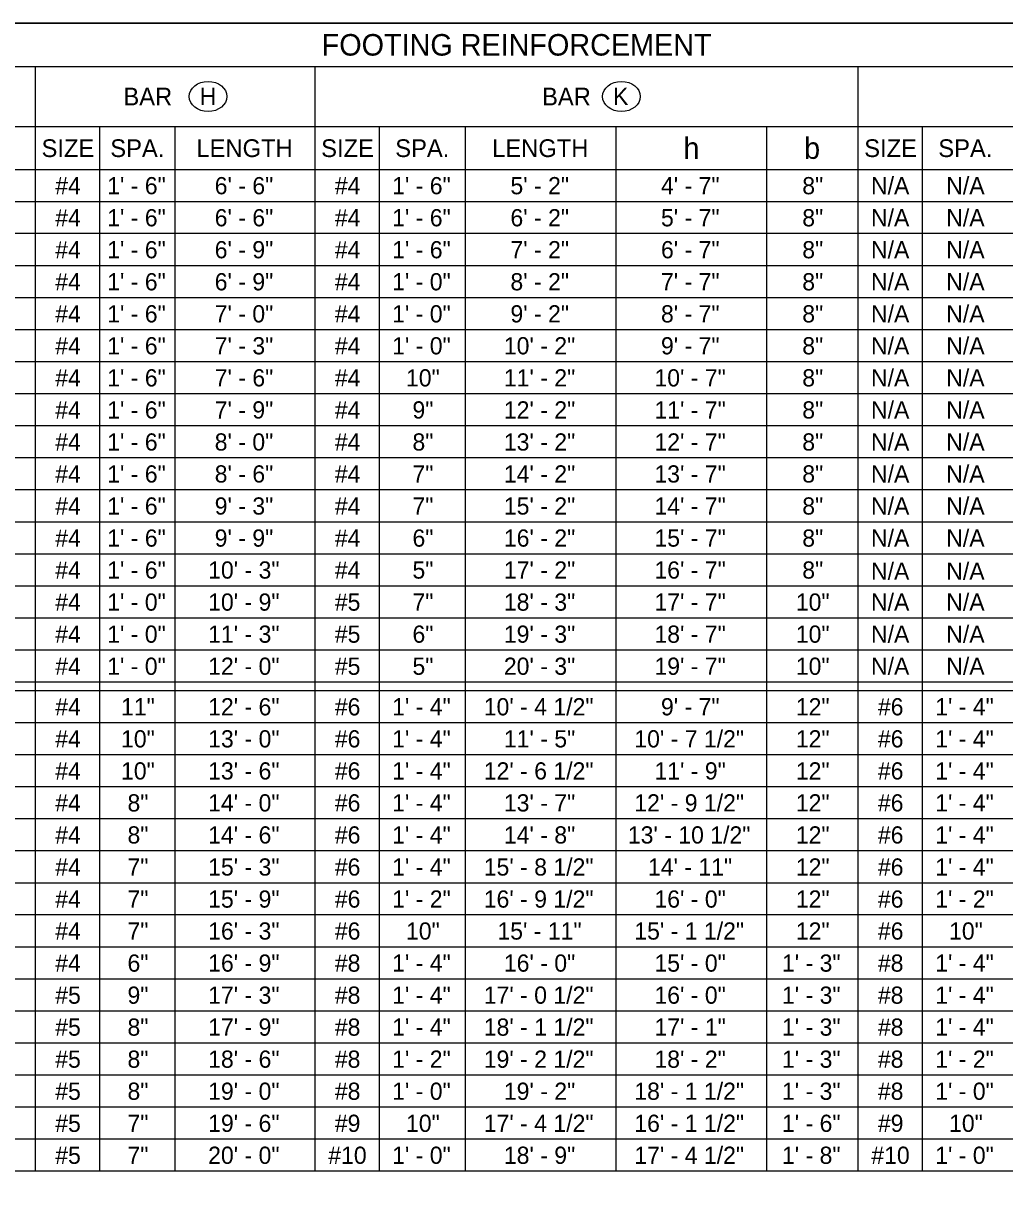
# Model space of a CAD drawing. Extents: x 99862 to 103151, y 100000 to 105076.
# Drawn here: x 100848 to 101760, y 103992 to 105076 of the extents above; entities that cross this region are included whole.
import ezdxf

# ---------------------------------------------------------------- set-up
doc = ezdxf.new("R2010")
doc.units = 0
for name, color, linetype in [('Level 1', 7, 'Continuous'), ('Level 20', 7, 'Continuous'), ('Level 4', 7, 'Continuous')]:
    doc.layers.add(name, color=color, linetype=linetype)

msp = doc.modelspace()

# ---------------------------------------------------------------- linework, layer by layer
at = {"layer": 'Level 1'}
msp.add_lwpolyline([(99862, 102999.5), (103151, 102999.5), (103151, 105075.5), (99862, 105075.5)], close=True, dxfattribs=at)
at = {"layer": 'Level 20'}
for centre in [(101019.5, 105007.5), (101403.9, 105007.5)]:
    msp.add_ellipse(centre, major_axis=(-17.5, 0), ratio=0.8, dxfattribs=at)
at = {"layer": 'Level 4'}
for p, q in [((100399, 105035.5), (102539, 105035.5)), ((100859, 104008.6), (100859, 105035.5)), ((101119, 104008.6), (101119, 105035.5)), ((101624, 104008.6), (101624, 105035.5)), ((99999, 104979.5), (102711, 104979.5)), ((100919, 104008.6), (100919, 104979.5)), ((100989, 104008.6), (100989, 104979.5)), ((101179, 104008.6), (101179, 104979.5)), ((101259, 104008.6), (101259, 104979.5)), ((101399, 104008.6), (101399, 104979.5)), ((101539, 104008.6), (101539, 104979.5)), ((101684, 104008.6), (101684, 104979.5)), ((99924, 104939.5), (103151, 104939.5)), ((103151, 104909.7), (99924, 104909.7)), ((103151, 104880), (99924, 104880)), ((103151, 104850.2), (99924, 104850.2)), ((103151, 104820.4), (99924, 104820.4)), ((103151, 104790.6), (99924, 104790.6)), ((103151, 104760.9), (99924, 104760.9)), ((103151, 104731.1), (99924, 104731.1)), ((103151, 104701.3), (99924, 104701.3)), ((103151, 104671.6), (99924, 104671.6)), ((103151, 104641.8), (99924, 104641.8)), ((103151, 104612), (99924, 104612)), ((103151, 104582.2), (99924, 104582.2)), ((103151, 104552.5), (99924, 104552.5)), ((103151, 104522.7), (99924, 104522.7)), ((103151, 104492.9), (99924, 104492.9)), ((103151, 104463.2), (99924, 104463.2)), ((103151, 104455.2), (99924, 104455.2)), ((103151, 104425.4), (99924, 104425.4)), ((103151, 104395.6), (99924, 104395.6)), ((103151, 104365.8), (99924, 104365.8)), ((103151, 104336.1), (99924, 104336.1)), ((103151, 104306.3), (99924, 104306.3)), ((103151, 104276.5), (99924, 104276.5)), ((103151, 104246.8), (99924, 104246.8)), ((103151, 104217), (99924, 104217)), ((103151, 104187.2), (99924, 104187.2)), ((103151, 104157.4), (99924, 104157.4)), ((103151, 104127.7), (99924, 104127.7)), ((103151, 104097.9), (99924, 104097.9)), ((103151, 104068.1), (99924, 104068.1)), ((103151, 104038.4), (99924, 104038.4))]:
    msp.add_line(p, q, dxfattribs=at)
for points in [[(99924, 105075.5), (103151, 105075.5)], [(103151, 104008.6), (99924, 104008.6), (99924, 105075.5)]]:
    msp.add_lwpolyline(points, dxfattribs=at)

# ---------------------------------------------------------------- texts
at = {"layer": 'Level 20'}
for s, height, p in [('FOOTING REINFORCEMENT', 20, (101125.2, 105045.5)), ('BAR', 16.5, (100940.8, 104999.2)), ('H', 16, (101011.7, 104999.7)), ('BAR', 16.5, (101330.1, 104999.2)), ('K', 16, (101396.1, 104999.7)), ('SIZE', 16.5, (100864.7, 104951.2)), ('SPA.', 16.5, (100928.6, 104951.2)), ('LENGTH', 16.5, (101008.7, 104951.2)), ('SIZE', 16.5, (101124.7, 104951.2)), ('SPA.', 16.5, (101193.6, 104951.2)), ('LENGTH', 16.5, (101283.7, 104951.2)), ('h', 20, (101461.6, 104949.5)), ('b', 20, (101573.8, 104949.5)), ('SIZE', 16.5, (101629.7, 104951.2)), ('SPA.', 16.5, (101698.6, 104951.2))]:
    msp.add_text(s, height=height, dxfattribs=at).set_placement(p)
for s, p in [('N/A', (101636, 104916.6)), ('N/A', (101706, 104916.6)), ('N/A', (101636, 104886.8)), ('N/A', (101706, 104886.8)), ('N/A', (101636, 104857.1)), ('N/A', (101706, 104857.1)), ('N/A', (101636, 104827.3)), ('N/A', (101706, 104827.3)), ('N/A', (101636, 104797.5)), ('N/A', (101706, 104797.5)), ('N/A', (101636, 104767.8)), ('N/A', (101706, 104767.8)), ('N/A', (101636, 104738)), ('N/A', (101706, 104738)), ('N/A', (101636, 104708.2)), ('N/A', (101706, 104708.2)), ('N/A', (101636, 104678.4)), ('N/A', (101706, 104678.4)), ('N/A', (101636, 104648.7)), ('N/A', (101706, 104648.7)), ('N/A', (101636, 104618.9)), ('N/A', (101706, 104618.9)), ('N/A', (101636, 104589.1)), ('N/A', (101706, 104589.1)), ('5"', (101209.6, 104559.4)), ('N/A', (101636, 104558.3)), ('N/A', (101706, 104558.3)), ('7"', (101209.6, 104529.6)), ('N/A', (101636, 104529.6)), ('N/A', (101706, 104529.6)), ('6"', (101209.6, 104499.8)), ('N/A', (101636, 104499.8)), ('N/A', (101706, 104499.8)), ('5"', (101209.6, 104470)), ('N/A', (101636, 104470)), ('N/A', (101706, 104470)), ('1\' - 4"', (101190.7, 104432.3)), ('1\' - 4"', (101190.7, 104402.5)), ('1\' - 4"', (101190.7, 104372.7)), ('1\' - 4"', (101190.7, 104343)), ('1\' - 4"', (101190.7, 104313.2)), ('1\' - 4"', (101190.7, 104283.4)), ('1\' - 2"', (101190.7, 104253.6)), ('10"', (101203.6, 104223.9)), ('1\' - 4"', (101190.7, 104194.1)), ('1\' - 4"', (101190.7, 104164.3)), ('1\' - 4"', (101190.7, 104134.6)), ('1\' - 2"', (101190.7, 104104.8)), ('1\' - 0"', (101190.7, 104075)), ('10"', (101203.6, 104045.2)), ('1\' - 0"', (101190.7, 104015.5))]:
    msp.add_text(s, height=16, rotation=360, dxfattribs=at).set_placement(p)
at = {"layer": 'Level 4'}
for s, p in [('#4', (100877.4, 104916.6)), ('1\' - 6"', (100925.7, 104916.6)), ('6\' - 6"', (101025.7, 104916.6)), ('#4', (101137.4, 104916.6)), ('1\' - 6"', (101190.7, 104916.6)), ('4\' - 7"', (101440.7, 104916.6)), ('8"', (101572.1, 104916.6)), ('#4', (100877.4, 104886.8)), ('1\' - 6"', (100925.7, 104886.8)), ('6\' - 6"', (101025.7, 104886.8)), ('#4', (101137.4, 104886.8)), ('1\' - 6"', (101190.7, 104886.8)), ('5\' - 7"', (101440.7, 104886.8)), ('8"', (101572.1, 104886.8)), ('#4', (100877.4, 104857.1)), ('1\' - 6"', (100925.7, 104857.1)), ('6\' - 9"', (101025.7, 104857.1)), ('#4', (101137.4, 104857.1)), ('1\' - 6"', (101190.7, 104857.1)), ('6\' - 7"', (101440.7, 104857.1)), ('8"', (101572.1, 104857.1)), ('#4', (100877.4, 104827.3)), ('1\' - 6"', (100925.7, 104827.3)), ('6\' - 9"', (101025.7, 104827.3)), ('#4', (101137.4, 104827.3)), ('1\' - 0"', (101190.7, 104827.3)), ('7\' - 7"', (101440.7, 104827.3)), ('8"', (101572.1, 104827.3)), ('#4', (100877.4, 104797.5)), ('1\' - 6"', (100925.7, 104797.5)), ('7\' - 0"', (101025.7, 104797.5)), ('#4', (101137.4, 104797.5)), ('1\' - 0"', (101190.7, 104797.5)), ('8\' - 7"', (101440.7, 104797.5)), ('8"', (101572.1, 104797.5)), ('#4', (100877.4, 104767.8)), ('1\' - 6"', (100925.7, 104767.8)), ('7\' - 3"', (101025.7, 104767.8)), ('#4', (101137.4, 104767.8)), ('1\' - 0"', (101190.7, 104767.8)), ('9\' - 7"', (101440.7, 104767.8)), ('8"', (101572.1, 104767.8)), ('#4', (100877.4, 104738)), ('1\' - 6"', (100925.7, 104738)), ('7\' - 6"', (101025.7, 104738)), ('#4', (101137.4, 104738)), ('10"', (101203.6, 104738)), ('10\' - 7"', (101434.6, 104738)), ('8"', (101572.1, 104738)), ('#4', (100877.4, 104708.2)), ('1\' - 6"', (100925.7, 104708.2)), ('7\' - 9"', (101025.7, 104708.2)), ('#4', (101137.4, 104708.2)), ('9"', (101209.6, 104708.2)), ('11\' - 7"', (101434.6, 104708.2)), ('8"', (101572.1, 104708.2)), ('#4', (100877.4, 104678.4)), ('1\' - 6"', (100925.7, 104678.4)), ('8\' - 0"', (101025.7, 104678.4)), ('#4', (101137.4, 104678.4)), ('8"', (101209.6, 104678.4)), ('12\' - 7"', (101434.6, 104678.4)), ('8"', (101572.1, 104678.4)), ('#4', (100877.4, 104648.7)), ('1\' - 6"', (100925.7, 104648.7)), ('8\' - 6"', (101025.7, 104648.7)), ('#4', (101137.4, 104648.7)), ('7"', (101209.6, 104648.7)), ('13\' - 7"', (101434.6, 104648.7)), ('8"', (101572.1, 104648.7)), ('#4', (100877.4, 104618.9)), ('1\' - 6"', (100925.7, 104618.9)), ('9\' - 3"', (101025.7, 104618.9)), ('#4', (101137.4, 104618.9)), ('7"', (101209.6, 104618.9)), ('14\' - 7"', (101434.6, 104618.9)), ('8"', (101572.1, 104618.9)), ('#4', (100877.4, 104589.1)), ('1\' - 6"', (100925.7, 104589.1)), ('9\' - 9"', (101025.7, 104589.1)), ('#4', (101137.4, 104589.1)), ('6"', (101209.6, 104589.1)), ('15\' - 7"', (101434.6, 104589.1)), ('8"', (101572.1, 104589.1)), ('#4', (100877.4, 104559.4)), ('1\' - 6"', (100925.7, 104559.4)), ('10\' - 3"', (101019.6, 104559.4)), ('#4', (101137.4, 104559.4)), ('16\' - 7"', (101434.6, 104559.4)), ('8"', (101572.1, 104559.4)), ('#4', (100877.4, 104529.6)), ('1\' - 0"', (100925.7, 104529.6)), ('10\' - 9"', (101019.6, 104529.6)), ('#5', (101137.4, 104529.6)), ('17\' - 7"', (101434.6, 104529.6)), ('10"', (101566.1, 104529.6)), ('#4', (100877.4, 104499.8)), ('1\' - 0"', (100925.7, 104499.8)), ('11\' - 3"', (101019.6, 104499.8)), ('#5', (101137.4, 104499.8)), ('18\' - 7"', (101434.6, 104499.8)), ('10"', (101566.1, 104499.8)), ('#4', (100877.4, 104470)), ('1\' - 0"', (100925.7, 104470)), ('12\' - 0"', (101019.6, 104470)), ('#5', (101137.4, 104470)), ('19\' - 7"', (101434.6, 104470)), ('10"', (101566.1, 104470)), ('#4', (100877.4, 104432.3)), ('11"', (100938.6, 104432.3)), ('12\' - 6"', (101019.6, 104432.3)), ('#6', (101137.4, 104432.3)), ('12"', (101566.1, 104432.3)), ('#6', (101642.4, 104432.3)), ('1\' - 4"', (101695.7, 104432.3)), ('#4', (100877.4, 104402.5)), ('10"', (100938.6, 104402.5)), ('13\' - 0"', (101019.6, 104402.5)), ('#6', (101137.4, 104402.5)), ('12"', (101566.1, 104402.5)), ('#6', (101642.4, 104402.5)), ('1\' - 4"', (101695.7, 104402.5)), ('#4', (100877.4, 104372.7)), ('10"', (100938.6, 104372.7)), ('13\' - 6"', (101019.6, 104372.7)), ('#6', (101137.4, 104372.7)), ('12"', (101566.1, 104372.7)), ('#6', (101642.4, 104372.7)), ('1\' - 4"', (101695.7, 104372.7)), ('#4', (100877.4, 104343)), ('8"', (100944.6, 104343)), ('14\' - 0"', (101019.6, 104343)), ('#6', (101137.4, 104343)), ('12"', (101566.1, 104343)), ('#6', (101642.4, 104343)), ('1\' - 4"', (101695.7, 104343)), ('#4', (100877.4, 104313.2)), ('8"', (100944.6, 104313.2)), ('14\' - 6"', (101019.6, 104313.2)), ('#6', (101137.4, 104313.2)), ('12"', (101566.1, 104313.2)), ('#6', (101642.4, 104313.2)), ('1\' - 4"', (101695.7, 104313.2)), ('#4', (100877.4, 104283.4)), ('7"', (100944.6, 104283.4)), ('15\' - 3"', (101019.6, 104283.4)), ('#6', (101137.4, 104283.4)), ('12"', (101566.1, 104283.4)), ('#6', (101642.4, 104283.4)), ('1\' - 4"', (101695.7, 104283.4)), ('#4', (100877.4, 104253.6)), ('7"', (100944.6, 104253.6)), ('15\' - 9"', (101019.6, 104253.6)), ('#6', (101137.4, 104253.6)), ('12"', (101566.1, 104253.6)), ('#6', (101642.4, 104253.6)), ('1\' - 2"', (101695.7, 104253.6)), ('#4', (100877.4, 104223.9)), ('7"', (100944.6, 104223.9)), ('16\' - 3"', (101019.6, 104223.9)), ('#6', (101137.4, 104223.9)), ('12"', (101566.1, 104223.9)), ('#6', (101642.4, 104223.9)), ('10"', (101708.6, 104223.9)), ('#4', (100877.4, 104194.1)), ('6"', (100944.6, 104194.1)), ('16\' - 9"', (101019.6, 104194.1)), ('#8', (101137.4, 104194.1)), ('1\' - 3"', (101553.2, 104194.1)), ('#8', (101642.4, 104194.1)), ('1\' - 4"', (101695.7, 104194.1)), ('#5', (100877.4, 104164.3)), ('9"', (100944.6, 104164.3)), ('17\' - 3"', (101019.6, 104164.3)), ('#8', (101137.4, 104164.3)), ('1\' - 3"', (101553.2, 104164.3)), ('#8', (101642.4, 104164.3)), ('1\' - 4"', (101695.7, 104164.3)), ('#5', (100877.4, 104134.6)), ('8"', (100944.6, 104134.6)), ('17\' - 9"', (101019.6, 104134.6)), ('#8', (101137.4, 104134.6)), ('1\' - 3"', (101553.2, 104134.6)), ('#8', (101642.4, 104134.6)), ('1\' - 4"', (101695.7, 104134.6)), ('#5', (100877.4, 104104.8)), ('8"', (100944.6, 104104.8)), ('18\' - 6"', (101019.6, 104104.8)), ('#8', (101137.4, 104104.8)), ('1\' - 3"', (101553.2, 104104.8)), ('#8', (101642.4, 104104.8)), ('1\' - 2"', (101695.7, 104104.8)), ('#5', (100877.4, 104075)), ('8"', (100944.6, 104075)), ('19\' - 0"', (101019.6, 104075)), ('#8', (101137.4, 104075)), ('1\' - 3"', (101553.2, 104075)), ('#8', (101642.4, 104075)), ('1\' - 0"', (101695.7, 104075)), ('#5', (100877.4, 104045.2)), ('7"', (100944.6, 104045.2)), ('19\' - 6"', (101019.6, 104045.2)), ('#9', (101137.4, 104045.2)), ('1\' - 6"', (101553.2, 104045.2)), ('#9', (101642.4, 104045.2)), ('10"', (101708.6, 104045.2)), ('#5', (100877.4, 104015.5)), ('7"', (100944.6, 104015.5)), ('20\' - 0"', (101019.6, 104015.5)), ('#10', (101131.3, 104015.5)), ('1\' - 8"', (101553.2, 104015.5)), ('#10', (101636.3, 104015.5)), ('1\' - 0"', (101695.7, 104015.5))]:
    msp.add_text(s, height=16, rotation=360, dxfattribs=at).set_placement(p)
for s, p in [('5\' - 2"', (101300.7, 104916.6)), ('6\' - 2"', (101300.7, 104886.8)), ('7\' - 2"', (101300.7, 104857.1)), ('8\' - 2"', (101300.7, 104827.3)), ('9\' - 2"', (101300.7, 104797.5)), ('10\' - 2"', (101294.6, 104767.8)), ('11\' - 2"', (101294.6, 104738)), ('12\' - 2"', (101294.6, 104708.2)), ('13\' - 2"', (101294.6, 104678.4)), ('14\' - 2"', (101294.6, 104648.7)), ('15\' - 2"', (101294.6, 104618.9)), ('16\' - 2"', (101294.6, 104589.1)), ('17\' - 2"', (101294.6, 104559.4)), ('18\' - 3"', (101294.6, 104529.6)), ('19\' - 3"', (101294.6, 104499.8)), ('20\' - 3"', (101294.6, 104470)), ('10\' - 4 1/2"', (101275.9, 104432.3)), ('9\' - 7"', (101440.7, 104432.3)), ('11\' - 5"', (101294.6, 104402.5)), ('10\' - 7 1/2"', (101415.9, 104402.5)), ('12\' - 6 1/2"', (101275.9, 104372.7)), ('11\' - 9"', (101434.6, 104372.7)), ('13\' - 7"', (101294.6, 104343)), ('12\' - 9 1/2"', (101415.9, 104343)), ('14\' - 8"', (101294.6, 104313.2)), ('13\' - 10 1/2"', (101409.9, 104313.2)), ('15\' - 8 1/2"', (101275.9, 104283.4)), ('14\' - 11"', (101428.6, 104283.4)), ('16\' - 9 1/2"', (101275.9, 104253.6)), ('16\' - 0"', (101434.6, 104253.6)), ('15\' - 11"', (101288.6, 104223.9)), ('15\' - 1 1/2"', (101415.9, 104223.9)), ('16\' - 0"', (101294.6, 104194.1)), ('15\' - 0"', (101434.6, 104194.1)), ('17\' - 0 1/2"', (101275.9, 104164.3)), ('16\' - 0"', (101434.6, 104164.3)), ('18\' - 1 1/2"', (101275.9, 104134.6)), ('17\' - 1"', (101434.6, 104134.6)), ('19\' - 2 1/2"', (101275.9, 104104.8)), ('18\' - 2"', (101434.6, 104104.8)), ('19\' - 2"', (101294.6, 104075)), ('18\' - 1 1/2"', (101415.9, 104075)), ('17\' - 4 1/2"', (101275.9, 104045.2)), ('16\' - 1 1/2"', (101415.9, 104045.2)), ('18\' - 9"', (101294.6, 104015.5)), ('17\' - 4 1/2"', (101415.9, 104015.5))]:
    msp.add_text(s, height=16, dxfattribs=at).set_placement(p)

doc.saveas('drawing.dxf')
